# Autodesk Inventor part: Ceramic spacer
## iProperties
Shininess: 64.0
Length Units: 11272
Angle Units: 11279
Time Units: 11290
Mass Units: 11286
Length Display Precision: 3
Angle Display Precision: 2
Compacted: True
Part Number: Ceramic spacer
Document SubType Name: Modeling
Created: 2003-07
Designer: jpittman
Manufacturer: Standard
Standards Organization: Custom
Density: 0.0
Volumn: 0.0
Area: 0.0
PropertySet Name: Model Information
Control State: 0
Master: False
Checked Out: False
Author: jpittman
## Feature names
1. Extrusion1
2. Fillet1
3. Hole1
4. Revolution1
5. Circular Pattern1
